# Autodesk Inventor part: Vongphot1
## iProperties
Created: 2011-05
Part Number: Vongphot1
Document SubType Name: Modeling
Designer: 904Chiaki
Density: 1 g/cm^3
Mass: 6.59028 g
Surface Area: 36.9866 cm^2
Volume: 6.59028 cm^3
Author: 904Chiaki
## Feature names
1. Revolution1
